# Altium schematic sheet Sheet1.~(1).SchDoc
size A
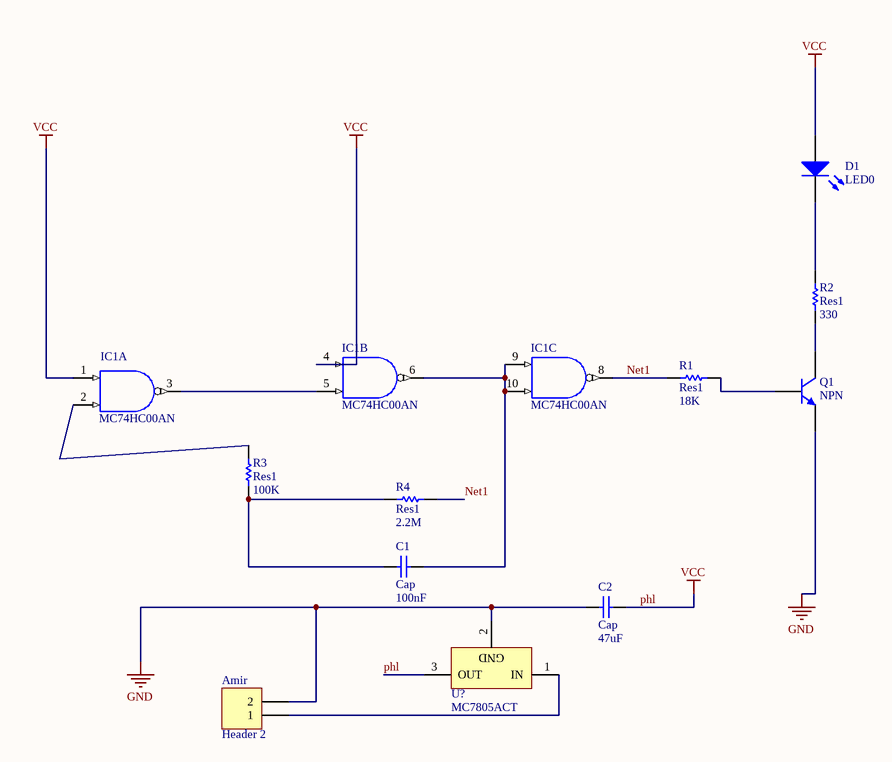
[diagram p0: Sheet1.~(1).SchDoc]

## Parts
Amir  Header 2  [HDR1X2]
C1  Cap  value 100nF  [RAD-0.3]
C2  Cap  value 47uF  [RAD-0.3]
D1  LED0  [RB5-10.5]
IC1  MC74HC00AN  [646-06]  (parts A,B,C of 4)
Q1  NPN  [HDR1X3]
R1  Res1  value 18K  [AXIAL-0.3]
R2  Res1  value 330  [AXIAL-0.3]
R3  Res1  value 100K  [AXIAL-0.3]
R4  Res1  value 2.2M  [AXIAL-0.3]
U?  MC7805ACT  [221A-04]

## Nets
GND: Amir.2 C2.1 IC1.7(GND) Q1.3(E) U?.2(GND)
phl: C2.2 D1.1(A) IC1.1(A) IC1.4(A) U?.3(OUT)  [also labelled VCC]
VDD: IC1.14(VDD)
Net1: IC1.8(Y) R1.1 R4.2
NetAmir_1: Amir.1 U?.1(IN)
NetC1_1: C1.1 R3.1 R4.1
NetC1_2: C1.2 IC1.6(Y) IC1.9(A) IC1.10(B)
NetD1_2: D1.2(K) R2.2
NetIC1_2: IC1.2(B) R3.2
NetIC1_3: IC1.3(Y) IC1.5(B)
NetQ1_1: Q1.1(C) R2.1
NetQ1_2: Q1.2(B) R1.2

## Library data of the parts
Amir = Header 2: Header, 2-Pin
C1 C2 = Cap: Capacitor
D1 = LED0: Typical INFRARED GaAs LED
IC1 = MC74HC00AN: Quad 2-Input NAND Gate
Q1 = NPN: NPN Bipolar Transistor
R1-R4 = Res1: Resistor
U? = MC7805ACT: 3-Terminal Positive Fixed Voltage Regulator; Note: Pin 2 is electrically connected to TAB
